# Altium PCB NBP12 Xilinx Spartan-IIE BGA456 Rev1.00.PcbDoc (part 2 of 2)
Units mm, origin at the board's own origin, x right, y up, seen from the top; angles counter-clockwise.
Board outline 69 x 80.99 mm, 4 copper layers (Top Layer, MidLayer1, InternalPlane1, Bottom Layer); 54 components, 265 nets, 866 pads, 396 vias.
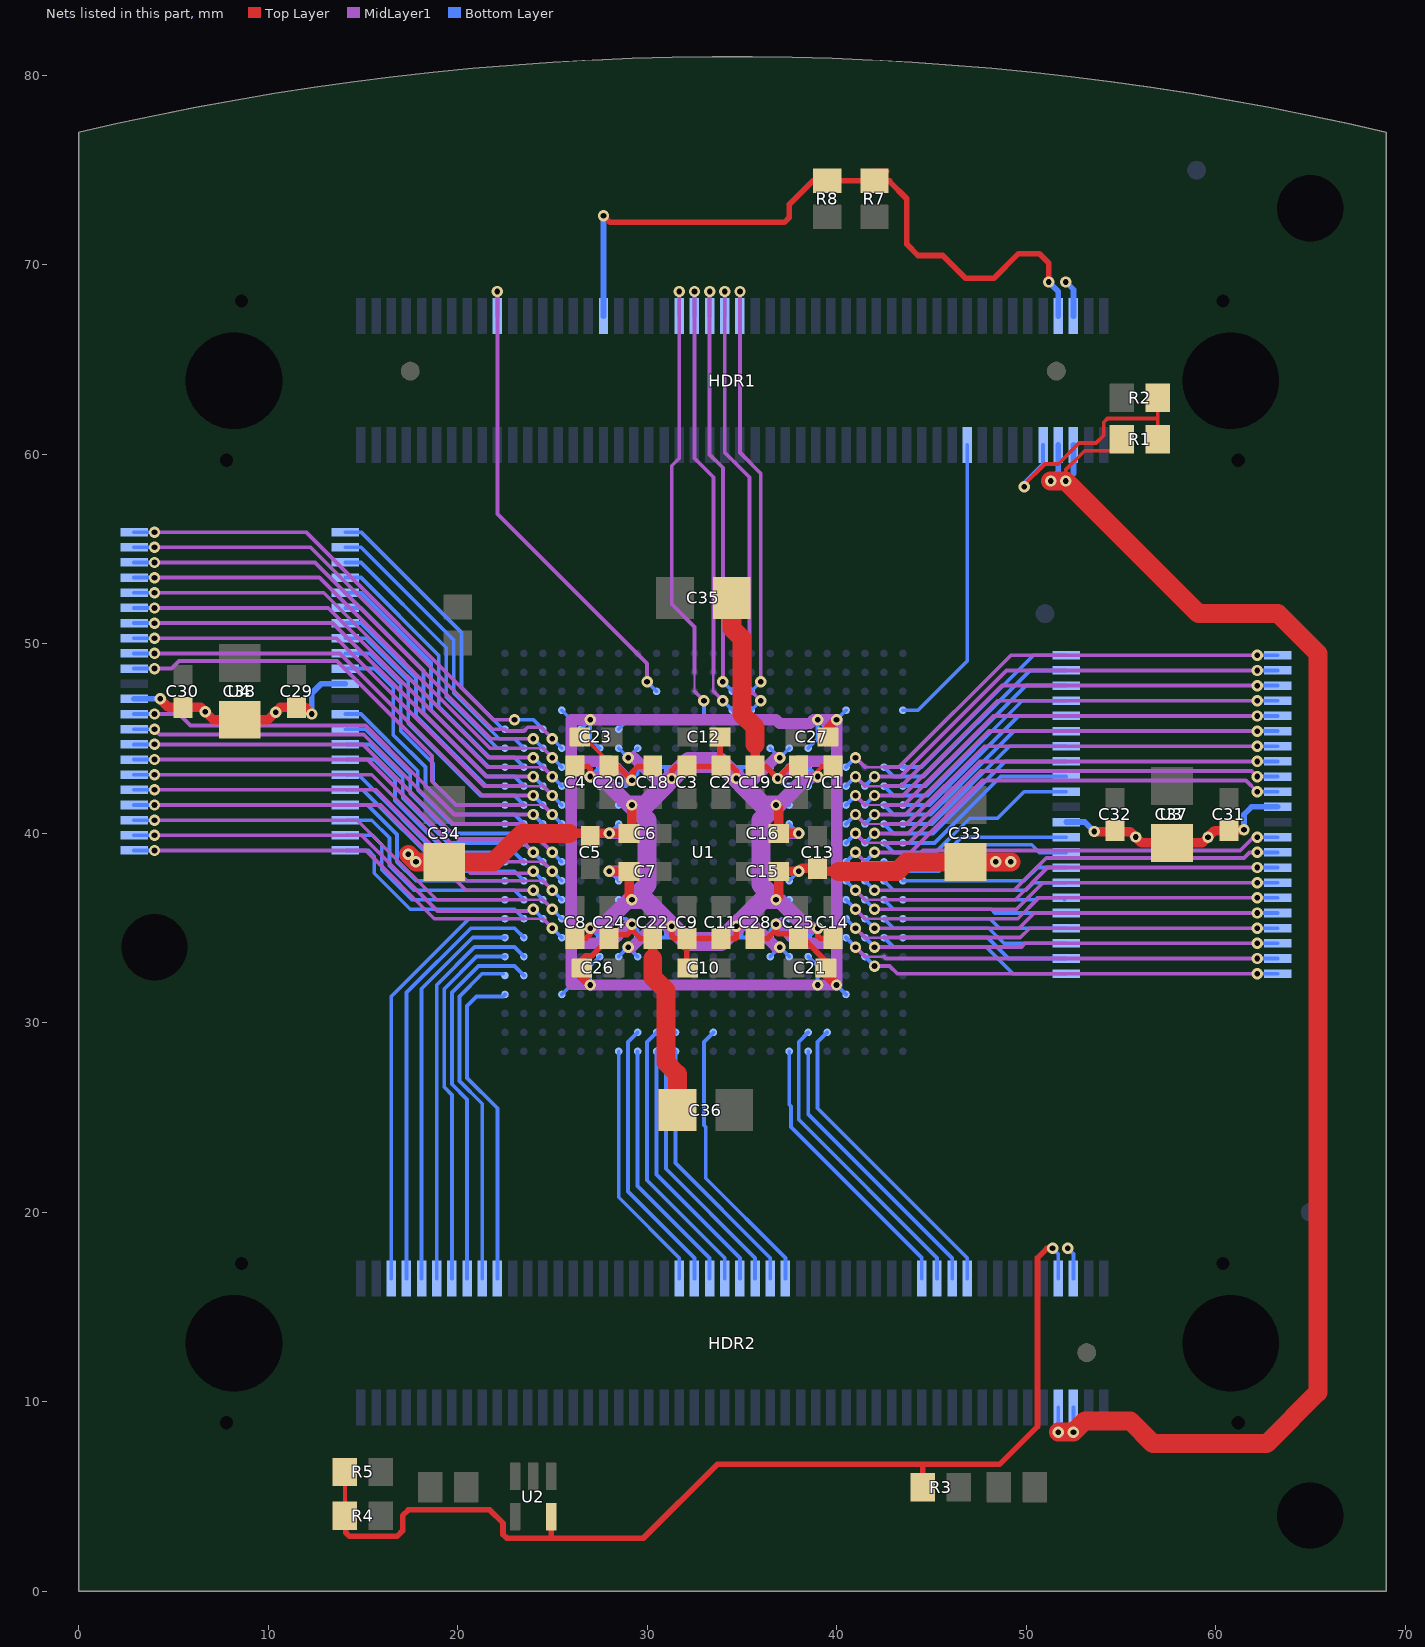
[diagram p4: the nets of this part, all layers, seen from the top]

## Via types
v1: diameter 0.6, hole 0.3, Top Layer to Bottom Layer, tented top, 396 vias

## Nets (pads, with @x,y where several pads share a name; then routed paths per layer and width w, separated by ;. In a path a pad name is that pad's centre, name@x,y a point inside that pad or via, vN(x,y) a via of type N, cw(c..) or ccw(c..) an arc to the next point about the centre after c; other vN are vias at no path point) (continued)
SP12: HDR2.82 U1.AA5 | length 16.5
  Bottom Layer w0.2: U1.AA5@39.5,29.5 39,29 39,25.5 46.9,17.6 HDR2.82@46.9,16.5
SP13: HDR2.80 U1.AB6 | length 15.1
  Bottom Layer w0.2: U1.AB6@38.5,28.5 38.5,25.2 46.1,17.6 HDR2.80@46.1,16.5
SP14: HDR2.78 U1.AA6 | length 16.2
  Bottom Layer w0.2: U1.AA6@38.5,29.5 38,29 38,24.9 45.3,17.6 HDR2.78@45.3,16.5
SP15: HDR2.76 U1.AB7 | length 14.9
  Bottom Layer w0.2: U1.AB7@37.5,28.5 37.5,25.7 37.6,25.6 37.6,24.5 44.5,17.6 HDR2.76@44.5,16.5
SPI_CLK: HDR1.46 U1.D10 | length 24.2
  MidLayer1 w0.127: 33.5,47.5 33.5,48.5
  MidLayer1 w0.2: v1(32.5,68.6) 32.5,59.8 33.5,58.8 33.5,48.5 ; 33.5,47.5 v1(34,47)
  Bottom Layer w0.2: HDR1.46@32.5,67.3 v1(32.5,68.6) ; v1(34,47) U1.D10@34.5,46.5
SPI_DIN: HDR1.44 U1.E16 | length 29.4
  MidLayer1 w0.127: 32.5,47.5 32.5,48.5
  MidLayer1 w0.2: v1(31.7,68.6) 31.7,59.8 31.3,59.4 31.3,52.1 32.5,50.9 32.5,48.5 ; 32.5,47.5 v1(33,47)
  Bottom Layer w0.2: U1.E16@28.5,45.5 29,46 32.8,46 33,46.2 v1(33,47) ; HDR1.44@31.7,67.3 v1(31.7,68.6)
SPI_DOUT: HDR1.50 U1.D9 | length 24.4
  MidLayer1 w0.2: v1(34.1,68.6) 34.1,60.1 35.4,58.8 35.4,47.6 v1(36,47)
  Bottom Layer w0.2: HDR1.50@34.1,67.3 v1(34.1,68.6) ; U1.D9@35.5,46.5 v1(36,47)
SPI_MODE: HDR1.52 U1.C9 | length 23.1
  MidLayer1 w0.2: v1(34.9,68.6) 34.9,60.1 36,59 v1(36,48)
  Bottom Layer w0.2: HDR1.52@34.9,67.3 v1(34.9,68.6) ; U1.C9@35.5,47.5 v1(36,48)
SPI_SEL: HDR1.48 U1.C10 | length 22.9
  MidLayer1 w0.2: v1(33.3,68.6) 33.3,60 34,59.3 v1(34,48)
  Bottom Layer w0.2: HDR1.48@33.3,67.3 v1(33.3,68.6) ; v1(34,48) U1.C10@34.5,47.5
SRAM0_A0: U1.J4 U3.5 | length 25.1
  MidLayer1 w0.127: 41.5,41.5 42.5,41.5
  MidLayer1 w0.2: v1(41,42) 41.5,41.5 ; 42.5,41.5 43.566,41.5 48.266,46.2 v1(62.2,46.2)
  Bottom Layer w0.2: U1.J4@40.5,41.5 v1(41,42) ; v1(62.2,46.2) U3.5@63.275,46.2
SRAM0_A1: U1.J3 U3.4 | length 24.1
  MidLayer1 w0.2: v1(42,42) 43.5,42 48.5,47 v1(62.2,47)
  Bottom Layer w0.2: U1.J3@41.5,41.5 v1(42,42) ; v1(62.2,47) U3.4@63.275,47
SRAM0_A2: U1.H4 U3.3 | length 25.4
  MidLayer1 w0.127: 41.5,42.5 42.5,42.5
  MidLayer1 w0.2: v1(41,43) 41.5,42.5 ; 42.5,42.5 43.434,42.5 48.734,47.8 v1(62.2,47.8)
  Bottom Layer w0.2: U1.H4@40.5,42.5 v1(41,43) ; v1(62.2,47.8) U3.3@63.275,47.8
SRAM0_A3: U1.H3 U3.2 | length 24.3
  MidLayer1 w0.2: v1(42,43) 43.369,43 48.969,48.6 v1(62.2,48.6)
  Bottom Layer w0.2: U1.H3@41.5,42.5 v1(42,43) ; v1(62.2,48.6) U3.2@63.275,48.6
SRAM0_A4: U1.G4 U3.1 | length 25.6
  MidLayer1 w0.127: 41.5,43.5 42.5,43.5
  MidLayer1 w0.2: v1(41,44) 41.5,43.5 ; 42.5,43.5 43.303,43.5 49.203,49.4 v1(62.2,49.4)
  Bottom Layer w0.2: U1.G4@40.5,43.5 v1(41,44) ; v1(62.2,49.4) U3.1@63.275,49.4
SRAM0_A5: U1.G1 U3.44 | length 11.1
  Bottom Layer w0.2: U1.G1@43.5,43.5 44.5,43.5 50.4,49.4 U3.44@52.125,49.4
SRAM0_A6: U1.G2 U3.43 | length 12.2
  Bottom Layer w0.2: U1.G2@42.5,43.5 43,43 44.6,43 50.2,48.6 U3.43@52.125,48.6
SRAM0_A7: U1.H1 U3.42 | length 10.8
  Bottom Layer w0.2: U1.H1@43.5,42.5 44.7,42.5 50,47.8 U3.42@52.125,47.8
SRAM0_A8: U1.P1 U3.28 | length 8.8
  Bottom Layer w0.2: U1.P1@43.5,36.5 50.5,36.5 50.6,36.6 U3.28@52.125,36.6 U3.28@52.025,36.5
SRAM0_A9: U1.P2 U3.27 | length 9.9
  Bottom Layer w0.2: U1.P2@42.5,36.5 43,36 48.163,36 48.363,35.8 U3.27@52.125,35.8
SRAM0_A10: U1.R1 U3.26 | length 8.8
  Bottom Layer w0.2: U1.R1@43.5,35.5 48.097,35.5 48.597,35 U3.26@52.125,35
SRAM0_A11: U1.R2 U3.25 | length 10.2
  Bottom Layer w0.2: U1.R2@42.5,35.5 43,35 48.031,35 48.831,34.2 U3.25@52.125,34.2
SRAM0_A12: U1.T1 U3.24 | length 9.1
  Bottom Layer w0.2: U1.T1@43.5,34.5 47.966,34.5 49.066,33.4 U3.24@52.125,33.4
SRAM0_A13: U1.T2 U3.23 | length 10.4
  Bottom Layer w0.2: U1.T2@42.5,34.5 43,34 47.9,34 49.3,32.6 U3.23@52.125,32.6
SRAM0_A14: U1.U3 U3.22 | length 22.1
  MidLayer1 w0.2: v1(42,33) 42.8,33 43.2,32.6 v1(62.2,32.6)
  Bottom Layer w0.2: U1.U3@41.5,33.5 v1(42,33) ; v1(62.2,32.6) U3.22@63.275,32.6
SRAM0_A15: U1.T4 U3.21 | length 23.2
  MidLayer1 w0.127: 41.5,33.5 42.5,33.5
  MidLayer1 w0.2: v1(41,34) 41.5,33.5 ; 42.5,33.5 42.6,33.4 v1(62.2,33.4)
  Bottom Layer w0.2: U1.T4@40.5,34.5 v1(41,34) ; v1(62.2,33.4) U3.21@63.275,33.4
SRAM0_A16: U1.T3 U3.20 | length 22.1
  MidLayer1 w0.2: v1(42,34) 49.76,34 49.96,34.2 v1(62.2,34.2)
  Bottom Layer w0.2: U1.T3@41.5,34.5 v1(42,34) ; v1(62.2,34.2) U3.20@63.275,34.2
SRAM0_A17: U1.R4 U3.19 | length 23.4
  MidLayer1 w0.127: 41.5,34.5 42.5,34.5
  MidLayer1 w0.2: v1(41,35) 41.5,34.5 ; 42.5,34.5 49.694,34.5 50.194,35 v1(62.2,35)
  Bottom Layer w0.2: U1.R4@40.5,35.5 v1(41,35) ; v1(62.2,35) U3.19@63.275,35
SRAM0_A18: U1.R3 U3.18 | length 22.3
  MidLayer1 w0.2: v1(42,35) 49.628,35 50.428,35.8 v1(62.2,35.8)
  Bottom Layer w0.2: U1.R3@41.5,35.5 v1(42,35) ; v1(62.2,35.8) U3.18@63.275,35.8
SRAM0_D0: U1.K4 U3.7 | length 24.9
  MidLayer1 w0.127: 41.5,40.5 42.5,40.5
  MidLayer1 w0.2: v1(41,41) 41.5,40.5 ; 42.5,40.5 43.697,40.5 47.797,44.6 v1(62.2,44.6)
  Bottom Layer w0.2: U1.K4@40.5,40.5 v1(41,41) ; v1(62.2,44.6) U3.7@63.275,44.6
SRAM0_D1: U1.L3 U3.8 | length 23.6
  MidLayer1 w0.2: v1(42,40) 43.763,40 46.034,42.271 47.563,43.8 v1(62.2,43.8)
  Bottom Layer w0.2: U1.L3@41.5,39.5 v1(42,40) ; v1(62.2,43.8) U3.8@63.275,43.8
SRAM0_D2: U1.L4 U3.9 | length 24.9
  MidLayer1 w0.127: 41.5,39.5 42.5,39.5
  MidLayer1 w0.2: v1(41,40) 41.5,39.5 ; 42.5,39.5 43.828,39.5 47.628,43.3 61.9,43.3 v1(62.2,43)
  Bottom Layer w0.2: U1.L4@40.5,39.5 v1(41,40) ; v1(62.2,43) U3.9@63.275,43
SRAM0_D3: U1.M3 U3.10 | length 23.8
  MidLayer1 w0.2: v1(42,39) 43.894,39 47.694,42.8 61.6,42.8 v1(62.2,42.2)
  Bottom Layer w0.2: U1.M3@41.5,38.5 v1(42,39) ; v1(62.2,42.2) U3.10@63.275,42.2
SRAM0_D4: U1.M4 U3.13 | length 23.8
  MidLayer1 w0.2: v1(41,39) 41.564,38.436 43.896,38.436 44.56,39.1 61.3,39.1 62,39.8 v1(62.2,39.8)
  Bottom Layer w0.2: U1.M4@40.5,38.5 v1(41,39) ; v1(62.2,39.8) U3.13@63.275,39.8
SRAM0_D5: U1.N3 U3.14 | length 22.8
  MidLayer1 w0.2: v1(42,37) 49.366,37 51.066,38.7 61.5,38.7 61.8,39 v1(62.2,39)
  Bottom Layer w0.2: U1.N3@41.5,37.5 v1(42,37) ; v1(62.2,39) U3.14@63.275,39
SRAM0_D6: U1.N4 U3.15 | length 23.9
  MidLayer1 w0.127: 41.5,36.5 42.5,36.5
  MidLayer1 w0.2: v1(41,37) 41.5,36.5 ; 42.5,36.5 49.431,36.5 51.131,38.2 v1(62.2,38.2)
  Bottom Layer w0.2: U1.N4@40.5,37.5 v1(41,37) ; v1(62.2,38.2) U3.15@63.275,38.2
SRAM0_D7: U1.P3 U3.16 | length 22.6
  MidLayer1 w0.2: v1(42,36) 49.497,36 50.897,37.4 v1(62.2,37.4)
  Bottom Layer w0.2: U1.P3@41.5,36.5 v1(42,36) ; v1(62.2,37.4) U3.16@63.275,37.4
SRAM0_D8: U1.N2 U3.29 | length 10
  Bottom Layer w0.2: U1.N2@42.5,37.5 43,37 50,37 50.4,37.4 U3.29@52.125,37.4
SRAM0_D9: U1.N1 U3.30 | length 8.9
  Bottom Layer w0.2: U1.N1@43.5,37.5 49.9,37.5 50.6,38.2 U3.30@52.125,38.2
SRAM0_D10: U1.M2 U3.31 | length 10.6
  Bottom Layer w0.2: U1.M2@42.5,38.5 43,38 45.4,38 46.8,39.4 50.3,39.4 50.7,39 U3.31@52.125,39
SRAM0_D11: U1.M1 U3.32 | length 9.2
  Bottom Layer w0.2: U1.M1@43.5,38.5 45.294,38.5 46.594,39.8 U3.32@52.125,39.8
SRAM0_D12: U1.L2 U3.35 | length 11.2
  Bottom Layer w0.2: U1.L2@42.5,39.5 43,39 45.228,39 47.028,40.8 48.5,40.8 49.9,42.2 U3.35@52.125,42.2
SRAM0_D13: U1.L1 U3.36 | length 10.1
  Bottom Layer w0.2: U1.L1@43.5,39.5 45.163,39.5 48.663,43 U3.36@52.125,43
SRAM0_D14: U1.K2 U3.37 | length 11.4
  Bottom Layer w0.2: U1.K2@42.5,40.5 43,40 45.097,40 48.897,43.8 U3.37@52.125,43.8
SRAM0_D15: U1.K1 U3.38 | length 10.3
  Bottom Layer w0.2: U1.K1@43.5,40.5 45.031,40.5 49.131,44.6 U3.38@52.125,44.6
SRAM0_E: U1.K3 U3.6 | length 23.8
  MidLayer1 w0.2: v1(42,41) 43.631,41 48.031,45.4 v1(62.2,45.4)
  Bottom Layer w0.2: U1.K3@41.5,40.5 v1(42,41) ; v1(62.2,45.4) U3.6@63.275,45.4
SRAM0_LB: U1.J2 U3.39 | length 11.7
  Bottom Layer w0.2: U1.J2@42.5,41.5 43,41 44.966,41 49.366,45.4 U3.39@52.125,45.4
SRAM0_OE: U1.H2 U3.41 | length 11.9
  Bottom Layer w0.2: U1.H2@42.5,42.5 43,42 44.8,42 49.8,47 U3.41@52.125,47
SRAM0_UB: U1.J1 U3.40 | length 10.6
  Bottom Layer w0.2: U1.J1@43.5,41.5 44.9,41.5 49.6,46.2 U3.40@52.125,46.2
SRAM0_W: U1.P4 U3.17 | length 23.6
  MidLayer1 w0.127: 41.5,35.5 42.5,35.5
  MidLayer1 w0.2: v1(41,36) 41.5,35.5 ; 42.5,35.5 49.563,35.5 50.663,36.6 v1(62.2,36.6)
  Bottom Layer w0.2: U1.P4@40.5,36.5 v1(41,36) ; v1(62.2,36.6) U3.17@63.275,36.6
SRAM1_A0: U1.G22 U4.5 | length 13.7
  Bottom Layer w0.2: U4.5@14.075,52.7 14.9,52.7 18.6,49 18.6,46.531 21.631,43.5 U1.G22@22.5,43.5
SRAM1_A1: U1.G21 U4.4 | length 15.2
  Bottom Layer w0.2: U4.4@14.075,53.5 14.9,53.5 19,49.4 19,46.697 21.697,44 23,44 U1.G21@23.5,43.5
SRAM1_A2: U1.F22 U4.3 | length 14
  Bottom Layer w0.2: U4.3@14.075,54.3 14.9,54.3 19.4,49.8 19.4,47.2 22.1,44.5 U1.F22@22.5,44.5
SRAM1_A3: U1.F21 U4.2 | length 15.5
  Bottom Layer w0.2: U4.2@14.075,55.1 14.9,55.1 19.8,50.2 19.8,47.4 22.2,45 23,45 U1.F21@23.5,44.5
SRAM1_A4: U1.E22 U4.1 | length 14.4
  Bottom Layer w0.2: U4.1@14.075,55.9 14.9,55.9 20.2,50.6 20.2,47.7 22.4,45.5 U1.E22@22.5,45.5
SRAM1_A5: U1.E20 U4.44 | length 26.6
  MidLayer1 w0.2: v1(4,55.9) 12,55.9 21.9,46 v1(23,46)
  Bottom Layer w0.2: U4.44@2.925,55.9 v1(4,55.9) ; v1(23,46) 24,46 ; 24,46 U1.E20@24.5,45.5 24,46
SRAM1_A6: U1.F19 U4.43 | length 27.1
  MidLayer1 w0.2: v1(4,55.1) 12.234,55.1 21.834,45.5 22.5,45.5 22.6,45.4 23.5,45.4 23.7,45.6 24.4,45.6 v1(25,45)
  Bottom Layer w0.2: U4.43@2.925,55.1 v1(4,55.1) ; v1(25,45) U1.F19@25.5,44.5
SRAM1_A7: U1.F20 U4.42 | length 25.6
  MidLayer1 w0.2: v1(4,54.3) 12.469,54.3 21.769,45 v1(24,45)
  Bottom Layer w0.2: U4.42@2.925,54.3 v1(4,54.3) ; v1(24,45) U1.F20@24.5,44.5
SRAM1_A8: U1.N20 U4.28 | length 24
  MidLayer1 w0.2: v1(4,43.1) 15.472,43.1 20.672,37.9 23.9,37.9 v1(24,38)
  Bottom Layer w0.2: U4.28@2.925,43.1 v1(4,43.1) ; v1(24,38) U1.N20@24.5,37.5
SRAM1_A9: U1.P19 U4.27 | length 25
  MidLayer1 w0.127: 23.5,37.5 24.5,37.5
  MidLayer1 w0.2: v1(4,42.3) 15.706,42.3 20.506,37.5 23.5,37.5 ; 24.5,37.5 v1(25,37)
  Bottom Layer w0.2: U4.27@2.925,42.3 v1(4,42.3) ; v1(25,37) U1.P19@25.5,36.5
SRAM1_A10: U1.P20 U4.26 | length 23.6
  MidLayer1 w0.2: v1(4,41.5) 15.94,41.5 20.44,37 v1(24,37)
  Bottom Layer w0.2: U4.26@2.925,41.5 v1(4,41.5) ; v1(24,37) U1.P20@24.5,36.5
SRAM1_A11: U1.R19 U4.25 | length 24.7
  MidLayer1 w0.127: 23.5,36.5 24.5,36.5
  MidLayer1 w0.2: v1(4,40.7) 14.7,40.7 18.9,36.5 23.5,36.5 ; 24.5,36.5 v1(25,36)
  Bottom Layer w0.2: U4.25@2.925,40.7 v1(4,40.7) ; v1(25,36) U1.R19@25.5,35.5
SRAM1_A12: U1.R20 U4.24 | length 23.5
  MidLayer1 w0.2: v1(4,39.9) 14.934,39.9 18.934,35.9 23.9,35.9 v1(24,36)
  Bottom Layer w0.2: U4.24@2.925,39.9 v1(4,39.9) ; v1(24,36) U1.R20@24.5,35.5
SRAM1_A13: U1.T19 U4.23 | length 24.5
  MidLayer1 w0.127: 23.5,35.5 24.5,35.5
  MidLayer1 w0.2: v1(4,39.1) 15.169,39.1 18.769,35.5 23.5,35.5 ; 24.5,35.5 v1(25,35)
  Bottom Layer w0.2: U4.23@2.925,39.1 v1(4,39.1) ; v1(25,35) U1.T19@25.5,34.5
SRAM1_A14: U1.R21 U4.22 | length 11.4
  Bottom Layer w0.2: U4.22@14.075,39.1 15.3,39.1 15.6,38.8 15.6,37.9 17.5,36 23,36 U1.R21@23.5,35.5
SRAM1_A15: U1.P22 U4.21 | length 10.6
  Bottom Layer w0.2: U4.21@14.075,39.9 15.5,39.9 16,39.4 16,38.1 17.6,36.5 U1.P22@22.5,36.5
SRAM1_A16: U1.P21 U4.20 | length 12
  Bottom Layer w0.2: U4.20@14.075,40.7 15.472,40.7 16.4,39.772 16.4,38.3 17.7,37 23,37 U1.P21@23.5,36.5
SRAM1_A17: U1.N22 U4.19 | length 10.9
  Bottom Layer w0.2: U4.19@14.075,41.5 15.237,41.5 16.8,39.937 16.8,38.5 17.8,37.5 U1.N22@22.5,37.5
SRAM1_A18: U1.N21 U4.18 | length 11.4
  Bottom Layer w0.2: U4.18@14.075,42.3 15.003,42.3 19.303,38 23,38 U1.N21@23.5,37.5
SRAM1_D0: U1.H22 U4.7 | length 13.2
  Bottom Layer w0.2: U4.7@14.075,51.1 14.9,51.1 17.8,48.2 17.8,46.2 21.5,42.5 U1.H22@22.5,42.5
SRAM1_D1: U1.J21 U4.8 | length 14.4
  Bottom Layer w0.2: U4.8@14.075,50.3 15.134,50.3 17.4,48.034 17.4,45.8 21.2,42 23,42 U1.J21@23.5,41.5
SRAM1_D2: U1.J22 U4.9 | length 13.8
  Bottom Layer w0.2: U4.9@14.075,49.5 15.369,49.5 17,47.869 17,45.4 18.7,43.7 18.7,42.7 19.9,41.5 U1.J22@22.5,41.5
SRAM1_D3: U1.K21 U4.10 | length 14.9
  Bottom Layer w0.2: U4.10@14.075,48.7 15.603,48.7 16.6,47.703 16.6,45.2 18.3,43.5 18.3,42.5 19.8,41 23,41 U1.K21@23.5,40.5
SRAM1_D4: U1.K22 U4.13 | length 11.4
  Bottom Layer w0.2: U4.13@14.075,46.3 14.9,46.3 17.9,43.3 17.9,42.3 19.7,40.5 U1.K22@22.5,40.5
SRAM1_D5: U1.L21 U4.14 | length 12.5
  Bottom Layer w0.2: U4.14@14.075,45.5 15.134,45.5 17.5,43.134 17.5,42.1 19.6,40 23,40 U1.L21@23.5,39.5
SRAM1_D6: U1.L22 U4.15 | length 11.2
  Bottom Layer w0.2: U4.15@14.075,44.7 15.369,44.7 17.1,42.969 17.1,41.9 19.5,39.5 U1.L22@22.5,39.5
SRAM1_D7: U1.M21 U4.16 | length 12.3
  Bottom Layer w0.2: U4.16@14.075,43.9 15.603,43.9 16.7,42.803 16.7,41.734 19.434,39 23,39 U1.M21@23.5,38.5
SRAM1_D8: U1.N19 U4.29 | length 25.2
  MidLayer1 w0.127: 23.5,38.5 24.5,38.5
  MidLayer1 w0.2: v1(4,43.9) 15.237,43.9 20.637,38.5 23.5,38.5 ; 24.5,38.5 v1(25,38)
  Bottom Layer w0.2: U4.29@2.925,43.9 v1(4,43.9) ; v1(25,38) U1.N19@25.5,37.5
SRAM1_D9: U1.M20 U4.30 | length 24.1
  MidLayer1 w0.2: v1(4,44.7) 15.003,44.7 20.003,39.7 23.3,39.7 v1(24,39)
  Bottom Layer w0.2: U4.30@2.925,44.7 v1(4,44.7) ; v1(24,39) U1.M20@24.5,38.5
SRAM1_D10: U1.M19 U4.31 | length 25.5
  MidLayer1 w0.2: v1(4,45.5) 4.275,45.225 15.044,45.225 19.769,40.5 23.5,40.5 v1(25,39)
  Bottom Layer w0.2: U4.31@2.925,45.5 v1(4,45.5) ; v1(25,39) U1.M19@25.5,38.5
SRAM1_D11: U1.K20 U4.32 | length 24
  MidLayer1 w0.2: v1(4,46.3) 5.3,46.3 5.9,45.7 15.134,45.7 17.634,43.2 19.834,41 v1(24,41)
  Bottom Layer w0.2: U4.32@2.925,46.3 v1(4,46.3) ; v1(24,41) U1.K20@24.5,40.5
SRAM1_D12: U1.K19 U4.35 | length 27.1
  MidLayer1 w0.127: 23.5,41.5 24.5,41.5
  MidLayer1 w0.2: v1(4,48.7) 4.9,48.7 5.3,49.1 13.634,49.1 18.649,44.085 18.649,42.751 19.9,41.5 23.5,41.5 ; 24.5,41.5 v1(25,41)
  Bottom Layer w0.2: U4.35@2.925,48.7 v1(4,48.7) ; v1(25,41) U1.K19@25.5,40.5
SRAM1_D13: U1.J20 U4.36 | length 24.9
  MidLayer1 w0.2: v1(4,49.5) 13.8,49.5 21.3,42 v1(24,42)
  Bottom Layer w0.2: U4.36@2.925,49.5 v1(4,49.5) ; v1(24,42) U1.J20@24.5,41.5
SRAM1_D14: U1.J19 U4.37 | length 26.2
  MidLayer1 w0.127: 23.5,42.5 24.5,42.5
  MidLayer1 w0.2: v1(4,50.3) 13.6,50.3 21.4,42.5 23.5,42.5 ; 24.5,42.5 v1(25,42)
  Bottom Layer w0.2: U4.37@2.925,50.3 v1(4,50.3) ; v1(25,42) U1.J19@25.5,41.5
SRAM1_D15: U1.H20 U4.38 | length 25.1
  MidLayer1 w0.2: v1(4,51.1) 13.406,51.1 21.506,43 v1(24,43)
  Bottom Layer w0.2: U4.38@2.925,51.1 v1(4,51.1) ; v1(24,43) U1.H20@24.5,42.5
SRAM1_E: U1.H21 U4.6 | length 14.6
  Bottom Layer w0.2: U4.6@14.075,51.9 14.9,51.9 18.2,48.6 18.2,46.366 21.566,43 23,43 U1.H21@23.5,42.5
SRAM1_LB: U1.H19 U4.39 | length 26.5
  MidLayer1 w0.127: 23.5,43.5 24.5,43.5
  MidLayer1 w0.2: v1(4,51.9) 13.172,51.9 21.572,43.5 23.5,43.5 ; 24.5,43.5 v1(25,43)
  Bottom Layer w0.2: U4.39@2.925,51.9 v1(4,51.9) ; v1(25,43) U1.H19@25.5,42.5
SRAM1_OE: U1.G19 U4.41 | length 26.7
  MidLayer1 w0.127: 23.5,44.5 24.5,44.5
  MidLayer1 w0.2: v1(4,53.5) 12.703,53.5 21.703,44.5 23.5,44.5 ; 24.5,44.5 v1(25,44)
  Bottom Layer w0.2: U4.41@2.925,53.5 v1(4,53.5) ; v1(25,44) U1.G19@25.5,43.5
SRAM1_UB: U1.G20 U4.40 | length 25.4
  MidLayer1 w0.2: v1(4,52.7) 12.937,52.7 21.637,44 v1(24,44)
  Bottom Layer w0.2: U4.40@2.925,52.7 v1(4,52.7) ; v1(24,44) U1.G20@24.5,43.5
SRAM1_W: U1.M22 U4.17 | length 10.3
  Bottom Layer w0.2: U4.17@14.075,43.1 14.769,43.1 19.369,38.5 U1.M22@22.5,38.5
SW0: HDR2.44 U1.AB16 | length 13.3
  Bottom Layer w0.2: U1.AB16@28.5,28.5 28.5,20.8 31.7,17.6 HDR2.44@31.7,16.5
SW1: HDR2.46 U1.AA15 | length 14.7
  Bottom Layer w0.2: U1.AA15@29.5,29.5 29,29 29,21.1 32.5,17.6 HDR2.46@32.5,16.5
SW2: HDR2.48 U1.AB15 | length 13.6
  Bottom Layer w0.2: U1.AB15@29.5,28.5 29.5,21.4 33.3,17.6 HDR2.48@33.3,16.5
SW3: HDR2.50 U1.AA14 | length 14.9
  Bottom Layer w0.2: U1.AA14@30.5,29.5 30,29 30,21.7 34.1,17.6 HDR2.50@34.1,16.5
SW4: HDR2.52 U1.AB14 | length 13.8
  Bottom Layer w0.2: U1.AB14@30.5,28.5 30.5,22 34.9,17.6 HDR2.52@34.9,16.5
SW5: HDR2.54 U1.AA13 | length 15.2
  Bottom Layer w0.2: U1.AA13@31.5,29.5 31,29 31,22.3 35.7,17.6 HDR2.54@35.7,16.5
SW6: HDR2.56 U1.AB13 | length 14.1
  Bottom Layer w0.2: U1.AB13@31.5,28.5 31.5,22.6 36.5,17.6 HDR2.56@36.5,16.5
SW7: HDR2.58 U1.AA11 | length 15
  Bottom Layer w0.2: U1.AA11@33.5,29.5 33,29 33,24.6 33.1,24.5 33.1,21.8 37.3,17.6 HDR2.58@37.3,16.5
SWC0: HDR2.18 U1.V22 | length 18.2
  Bottom Layer w0.2: HDR2.18@21.3,16.5 21.3,25.731 20.1,26.931 20.1,31.4 21.3,32.6 U1.V22@22.4,32.6
SWC1: HDR2.16 U1.V21 | length 20
  Bottom Layer w0.2: HDR2.16@20.5,16.5 20.5,25.966 19.7,26.766 19.7,31.6 21.1,33 23,33 U1.V21@23.5,32.5
SWC2: HDR2.14 U1.U22 | length 19.4
  Bottom Layer w0.2: HDR2.14@19.7,16.5 19.7,26.2 19.3,26.6 19.3,31.8 21,33.5 U1.U22@22.5,33.5
SWC3: HDR2.6 U1.R22 | length 22.6
  Bottom Layer w0.2: HDR2.6@16.5,16.5 16.5,31.4 20.6,35.5 U1.R22@22.5,35.5
SWR0: HDR2.20 U1.W22 | length 17.3
  Bottom Layer w0.2: HDR2.20@22.1,16.5 22.1,25.497 20.5,27.097 20.5,30.9 21,31.4 22.4,31.4 U1.W22@22.5,31.5
SWR1: HDR2.12 U1.U21 | length 21.1
  Bottom Layer w0.2: HDR2.12@18.9,16.5 18.9,32 20.9,34 23,34 U1.U21@23.5,33.5
SWR2: HDR2.10 U1.T22 | length 20.8
  Bottom Layer w0.2: HDR2.10@18.1,16.5 18.1,31.8 20.8,34.5 U1.T22@22.5,34.5
SWR3: HDR2.8 U1.T21 | length 22.9
  Bottom Layer w0.2: HDR2.8@17.3,16.5 17.3,31.6 20.7,35 23,35 U1.T21@23.5,34.5
TEST: HDR1.81 U1.D1 | length 15.9
  Bottom Layer w0.2: U1.D1@43.5,46.5 44.3,46.5 46.9,49.1 HDR1.81@46.9,60.5
VCC: C1.2 C2.2 C3.2 C4.2 C5.2 C6.2 C7.2 C8.2 C9.2 C10.2 C11.2 C12.2 C13.2 C14.2 C15.2 C16.2 C29.2 C30.2 C31.2 C32.2 C33.1 C34.1 C37.1 C38.1 HDR1.34 HDR1.94 HDR1.96 HDR2.94 HDR2.96 R3.1 R4.1 R5.1 R7.1 R8.1 U1.F7 U1.F8 U1.F15 U1.F16 U1.G6 U1.G9 U1.G10 U1.G13 U1.G14 U1.G17 U1.H6 U1.H17 U1.J7 U1.J16 U1.K7 U1.K16 U1.N7 U1.N16 U1.P7 U1.P16 U1.R6 U1.R17 U1.T6 U1.T9 U1.T10 U1.T13 U1.T14 U1.T17 U1.U7 U1.U8 U1.U15 U1.U16 U2.5 U3.11 U3.33 U4.11 U4.33 | length 272.9
  Top Layer w0.2: R4.1@14.05,4 R5.1@14.05,6.3 ; v1(39,43) 39,43.3 39.25,43.55
  Top Layer w0.3: R4.1@14.05,4 14.1,3.95 14.1,3.1 14.3,2.9 16.8,2.9 17.1,3.2 17.1,4 17.4,4.3 21.7,4.3 22.4,3.6 22.4,3 22.6,2.8 29.8,2.8 33.7,6.7 48.6,6.7 50.6,8.7 50.6,17.6 51.1,18.1 v1(51.4,18.1) ; 24.9,2.8 24.95,2.85 U2.5@24.95,3.925 ; C4.2@26.2,43.55 26.85,43.55 27,43.4 v1(27,43) ; 26.75,34.45 27,34.7 v1(27,35) ; v1(27.7,72.6) 28.05,72.25 37.25,72.25 37.5,72.5 37.5,73.2 38.75,74.45 R8.1@39.5,74.45 42.8,74.45 42.8,74.4 43.7,73.5 43.7,71.1 44.3,70.5 45.6,70.5 46.8,69.3 48.3,69.3 49.6,70.6 50.7,70.6 51.2,70.1 v1(51.2,69.1) ; v1(31.3,35.1) 31.3,34.6 31.45,34.45 C9.2@32.1,34.45 ; v1(31.3,42.9) 31.3,43.3 31.55,43.55 C3.2@32.1,43.55 C2.2@33.9,43.55 34.45,43.55 34.7,43.3 v1(34.7,42.9) ; C10.2@32.15,32.9 32.1,32.95 C9.2@32.1,34.45 ; C2.2@33.85,43.6 C12.2@33.85,45.1 ; v1(34.7,35.1) 34.7,34.5 34.65,34.45 C11.2@33.9,34.45 C9.2@32.1,34.45 ; v1(38,38) v1@38.15,38.15 ; v1(39,35) 39,34.6 39.15,34.45 C14.2@39.8,34.45 ; 39.25,43.55 C1.2@39.8,43.55 ; R7.1@42,74.95 R7.1@42.65,74.95 ; R3.1@44.55,5.5 44.55,6.65
  Top Layer w0.5: v1(4.3,47.1) 4.75,46.65 C30.2@5.5,46.65 6.45,46.65 7.1,46 C38.1@8.5,46 10,46 10.65,46.65 11.95,46.65 v1(12.3,46.3) ; 25.9,40 26.85,40 C5.2@27,39.85 27.15,40 C6.2@29.05,40 29.2,40.15 v1(29.2,41.5) ; v1(28,38) C7.2@29.05,38 29.05,36.65 v1(29.2,36.5) ; v1(36.8,36.5) 36.95,36.65 C15.2@36.95,38 v1(38,38) ; v1(36.8,41.5) 36.95,41.35 C16.2@36.95,40 v1(38,40) ; v1@38.15,38.15 C13.2@39,38.15 39.15,38 40.1,38 ; C33.1@46.8,38.5 v1(48.4,38.5) ; v1(53.6,40.1) 54.65,40.1 55.5,40.1 56.1,39.5 C37.1@57.7,39.5 59.3,39.5 59.95,40.15 C31.2@60.7,40.15 60.75,40.2 v1(61.5,40.2)
  Top Layer w1: v1(17.4,38.9) v1(17.8,38.5) 21.9,38.5 23.4,40 25.9,40 ; 40.1,38 43.2,38 43.7,38.5 C33.1@46.8,38.5 v1(48.4,38.5) v1(49.2,38.5)
  MidLayer1 w0.6: v1(27,35) 27.7,35 v1(29.2,36.5) ; v1(27,43) 27.7,43 29.8,40.9 ; 27.4,35 29.05,36.65 v1@29.2,36.8 ; 27.4,43 v1@29.1,41.3 ; v1(28,38) 29.8,38 ; v1(28,40) 29.8,40 ; v1(29,34) 29.2,34 30.8,35.6 ; v1(29,44) 29.3,44 30.841,42.459 30.841,42.441 ; v1(31.3,42.9) 31.9,43.5 34.1,43.5 v1(34.7,42.9) ; 35.202,35.602 35.202,35.598 36.8,34 v1(37,34) ; 35.22,42.38 35.22,42.42 36.8,44 v1(37,44) ; 36.2,40 v1(38,40) ; 36.8,41.2 36.95,41.35 38.6,43 ; v1(36.8,41.5) 38.3,43 v1(39,43) ; 38.6,35 37.1,36.5 v1(36.8,36.5) 38.3,35 v1(39,35)
  MidLayer1 w1: v1(29.2,36.5) 30,37.3 30,40.7 v1(29.2,41.5) 29.9,41.5 32.2,43.8 33.8,43.8 36.1,41.5 v1(36.8,41.5) 36,40.7 36,37.3 v1(36.8,36.5) 36.1,36.5 33.9,34.3 32.1,34.3 29.9,36.5 v1(29.2,36.5)
  Bottom Layer w0.2: U1.T17@27.5,34.5 v1(27,35) U1.R17@27.5,35.5 ; U1.H17@27.5,42.5 v1(27,43) U1.G17@27.5,43.5 ; v1(28,38) U1.N16@28.5,37.5 ; v1(28,40) U1.K16@28.5,40.5 ; U1.U16@28.5,33.5 v1(29,34) U1.U15@29.5,33.5 ; U1.P16@28.5,36.5 v1(29.2,36.5) ; U1.J16@28.5,41.5 v1(29.2,41.5) ; U1.F16@28.5,44.5 v1(29,44) U1.F15@29.5,44.5 ; U1.T14@30.5,34.5 U1.T13@31.5,34.5 ; U1.G14@30.5,43.5 U1.G13@31.5,43.5 ; 31,34.5 31,34.8 v1(31.3,35.1) ; 31,43.5 31,43.2 v1(31.3,42.9) ; U1.T10@34.5,34.5 U1.T9@35.5,34.5 ; U1.G10@34.5,43.5 U1.G9@35.5,43.5 ; v1(34.7,35.1) 35,34.8 35,34.5 ; v1(34.7,42.9) 35,43.2 35,43.5 ; U1.U8@36.5,33.5 v1(37,34) U1.U7@37.5,33.5 ; U1.F8@36.5,44.5 v1(37,44) U1.F7@37.5,44.5 ; v1(36.8,36.5) U1.P7@37.5,36.5 ; v1(36.8,41.5) U1.J7@37.5,41.5 ; U1.N7@37.5,37.5 v1(38,38) ; U1.K7@37.5,40.5 v1(38,40) ; U1.T6@38.5,34.5 v1(39,35) U1.R6@38.5,35.5 ; U1.H6@38.5,42.5 v1(39,43) U1.G6@38.5,43.5 ; v1(51.4,18.1) 51.7,17.8 HDR2.94@51.7,16.5 ; v1(52.2,18.1) 52.5,17.8 HDR2.96@52.5,16.5
  Bottom Layer w0.3: U4.33@2.925,47.1 v1(4.3,47.1) ; 12.3,46.6 12.3,47.4 12.8,47.9 U4.11@14.075,47.9 ; HDR1.34@27.7,67.3 v1(27.7,72.6) ; v1(51.2,69.1) 51.7,68.6 HDR1.94@51.7,67.3 ; v1(52.1,69.1) 52.5,68.7 HDR1.96@52.5,67.3 ; U3.33@52.125,40.6 53.1,40.6 v1(53.6,40.1) ; v1(61.5,40.2) 61.5,41 61.9,41.4 U3.11@63.275,41.4
  other v1: 55.786,39.814 59.6,39.8 10.4,46.4 6.679,46.421
VCCINT: C17.2 C18.2 C19.2 C20.2 C21.2 C22.2 C23.2 C24.2 C25.2 C26.2 C27.2 C28.2 C35.1 C36.1 HDR1.93 HDR1.95 HDR2.93 HDR2.95 R1.1 U1.D4 U1.D19 U1.E5 U1.E18 U1.F6 U1.F17 U1.G7 U1.G8 U1.G15 U1.G16 U1.H7 U1.H16 U1.R7 U1.R16 U1.T7 U1.T8 U1.T15 U1.T16 U1.U6 U1.U17 U1.V5 U1.V18 U1.W4 U1.W19 | length 222.3
  Top Layer w0.2: C23.2@26.65,45.1 C20.2@28.1,43.65 ; v1(52.1,58.6) 52.1,59.2 53.1,60.2 54.45,60.2 R1.1@55.05,60.8
  Top Layer w0.3: C26.2@26.55,33.35 26.75,33.55 27.1,33.55 28.198,34.648 28.948,34.648 v1@29.2,34.9 ; C20.2@28.45,43.55 v1(29.2,42.8) 29.2,43.2 29.55,43.55 C18.2@30.3,43.55 ; v1(29.2,35.2) v1@29.2,34.9 ; C22.2@30.3,34.45 29.65,34.45 29.2,34.9 ; C28.2@35.7,34.45 36.35,34.45 36.8,34.9 ; C19.2@35.7,43.55 36.25,43.55 v1(36.9,42.9) C17.2@37.55,43.55 ; v1(36.8,35.2) 36.8,34.8 36.9,34.7 38,34.7 C25.2@38,34.45 38.25,34.45 C21.2@39.45,33.25
  Top Layer w0.5: C26.2@26.55,32.9 26.55,32.45 v1(27,32) ; C22.2@30.3,33.9 C22.2@30.3,34.45 ; C19.2@35.7,43.55 35.7,44.3 ; C21.2@39.45,32.9 39.45,32.55 v1(39.997,32.003) ; C27.2@39.55,45.1 39.55,45.55 v1(40,46)
  Top Layer w1: 30.3,33.4 30.3,32.4 31,31.7 31,27.9 31.6,27.3 C36.1@31.6,25.4 ; C35.1@34.471,52.429 34.471,50.829 35,50.3 35,46.3 35.7,45.6 35.7,44.7 ; v1(51.3,58.6) v1(52.1,58.6) 59.1,51.6 63.3,51.6 65.4,49.5 65.4,10.5 62.7,7.8 56.7,7.8 55.5,9 53.1,9 v1(52.5,8.4) v1(51.7,8.4)
  MidLayer1 w0.6: 26,32.059 26,36.3 26,41.7 26,46 ; 26,34.2 28.031,34.2 29.031,35.2 v1(29.2,35.2) ; 26,43.8 28.031,43.8 29.031,42.8 v1(29.2,42.8) ; 26.029,32.029 v1@26.97,32.029 ; 26.031,46 35.869,46 36.8,46 37,45.8 38.6,45.8 38.8,46 v1(40,46) ; 29,32 v1(27,32) v1@40,32 ; v1(36.8,35.2) 36.969,35.2 37.969,34.2 40,34.2 ; v1@40,32.005 40,34.2 ; 40,43.8 37.969,43.8 v1@37.069,42.9 ; v1@40,45.831 v1(40,46) ; v1@37.069,42.9 v1(36.9,42.9) v1@37.069,42.9 ; 40,34.2 v1(40,46)
  Bottom Layer w0.2: U1.W19@25.5,31.5 26,32 v1(27,32) ; U1.D19@25.5,46.5 26,46 v1(27,46) ; U1.V18@26.5,32.5 v1(27,32) ; U1.E18@26.5,45.5 v1(27,46) ; U1.U17@27.5,33.5 27,33 v1(27,32) ; U1.F17@27.5,44.5 27,45 v1(27,46) ; U1.R16@28.5,35.5 28.9,35.5 v1(29.2,35.2) ; U1.H16@28.5,42.5 28.9,42.5 v1(29.2,42.8) ; U1.G16@28.5,43.5 v1(29.2,42.8) ; U1.T16@28.6,34.6 U1.T16@28.5,34.5 v1(29.2,35.2) ; U1.T15@29.5,34.5 29.5,34.9 v1(29.2,35.2) ; U1.G15@29.5,43.5 29.5,43.1 v1(29.2,42.8) ; U1.T8@36.5,34.5 36.5,34.9 v1(36.8,35.2) ; U1.G8@36.5,43.5 36.5,43.3 v1(36.9,42.9) ; U1.T7@37.5,34.5 v1(36.8,35.2) ; U1.R7@37.5,35.5 37.1,35.5 v1(36.8,35.2) ; U1.H7@37.5,42.5 37.3,42.5 v1(36.9,42.9) ; U1.G7@37.5,43.5 v1(36.9,42.9) ; U1.U6@38.5,33.5 39,33 ; U1.F6@38.5,44.5 39,45 v1(39,46) ; v1@39,32.2 39,33 ; U1.V5@39.5,32.5 v1(39.997,32.003) ; U1.E5@39.5,45.5 v1(39,46) ; v1@39.995,32 v1(39,32) 39,33 ; v1@40,32 U1.W4@40.5,31.5 ; U1.D4@40.5,46.5 v1(40,46) v1(39,46) ; v1(51.7,8.4) HDR2.93@51.7,9.7 ; v1(52.5,8.4) HDR2.95@52.5,9.7
  Bottom Layer w0.3: v1(51.3,58.6) 51.7,59 HDR1.93@51.7,60.5 ; v1(52.1,58.6) 52.5,59 HDR1.95@52.5,60.5
VDRIVE: HDR1.20 U1.C14 | length 25.9
  MidLayer1 w0.2: v1(22.1,68.6) 22.1,56.86 30,48.96 v1(30,48)
  Bottom Layer w0.2: HDR1.20@22.1,67.3 v1(22.1,68.6) ; v1(30,48) U1.C14@30.5,47.5
VREF: HDR1.91 R1.2 R2.1 | length 13.6
  Top Layer w0.2: v1(49.9,58.3) 49.9,58.4 51,59.5 51.7,59.5 52.8,60.6 53.7,60.6 54.1,61 54.1,61.7 54.3,61.9 56.9,61.9 56.95,61.95 ; R1.2@56.95,60.8 56.95,61.95 ; R2.1@56.95,63 56.95,61.95
  Bottom Layer w0.2: v1@49.9,58.5 50.9,59.5 HDR1.91@50.9,60.5
pads on no net: HDR1.MH1 HDR1.MH2 HDR1.MH3 HDR1.MH4 HDR1.MH5 HDR1.MH6 HDR2.MH1 HDR2.MH2 HDR2.MH3 HDR2.MH4 HDR2.MH5 HDR2.MH6 U1.C4 U1.D3 U1.D5 U1.D6 U1.D7 U1.D8 U1.D11 U1.D20 U1.D21 U1.D22 U1.E7 U1.E8 U1.E9 U1.E10 U1.E11 U1.E12 U1.E13 U1.E14 U1.E15 U1.E17 U1.E19 U1.E21 U1.F5 U1.F9 U1.F10 U1.F11 U1.F12 U1.F13 U1.F14 U1.F18 U1.G5 U1.G18 U1.H5 U1.H18 U1.J5 U1.J6 U1.J17 U1.J18 U1.K5 U1.K6 U1.K17 U1.K18 U1.L5 U1.L6 U1.L17 U1.L18 U1.L19 U1.L20 U1.M5 U1.M6 U1.M17 U1.M18 U1.N5 U1.N6 U1.N17 U1.N18 U1.P5 U1.P6 U1.P17 U1.P18 U1.R5 U1.R18 U1.T5 U1.T18 U1.U4 U1.U9 U1.U10 U1.U11 U1.U12 U1.U13 U1.U14 U1.V6 U1.V7 U1.V8 U1.V9 U1.V10 U1.V11 U1.V12 U1.V13 U1.V14 U1.V15 U1.V16 U1.V17 U2.1

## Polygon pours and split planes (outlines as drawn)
GND on Top Layer "Top Layer-GND" (solid, remove dead copper, pour order 1001): 0,0 0,82.2 69,82.2 69,0
VCCINT on Top Layer "Top Layer-VCCINT" (solid, remove dead copper, pour order 1000): 23,29 23,49.019 43,49.019 43,29
VCC on MidLayer1 "MidLayer1-VCC" (solid, remove dead copper, pour order 1003): 0,0 0,82.9 69,82.9 69,0
VCCINT on MidLayer1 "MidLayer1-VCCINT" (solid, remove dead copper, pour order 1002): 24,48 24,30 42,30 42,47.999 23.987,47.999
GND on Bottom Layer "Bottom Layer-GND" (solid, remove dead copper, pour order 1004): 0,0.1 0,82.2 69,82.2 69,0 0,0
GND on InternalPlane1 (split plane): 36.237,80.589 37.974,80.559 39.71,80.509 41.446,80.439 43.181,80.348 44.914,80.238 46.647,80.108 48.377,79.957 50.106,79.787 51.833,79.597 53.557,79.387 55.279,79.157 56.998,78.907 58.714,78.637 60.427,78.347 62.136,78.038 63.842,77.709 65.543,77.36 67.241,76.992 68.598,76.681 68.598,0.402 0.402,0.402 0.403,76.681 1.759,76.992 3.457,77.36 5.158,77.709 6.864,78.038 8.573,78.347 10.286,78.637 12.002,78.907 13.721,79.157 15.443,79.387 17.167,79.597 18.894,79.787 20.623,79.957 22.353,80.108 24.086,80.238 25.819,80.348 27.554,80.439 29.29,80.509 31.026,80.559 32.763,80.589 34.5,80.599
VCC on InternalPlane1 (split plane): 52.698,69.258 52.698,69 52.698,68.8 52.698,65.342 51.658,64.302 45.6,64.302 45.561,64.294 45.528,64.272 42.849,61.593 42.826,61.56 42.819,61.521 42.819,55.863 35.428,48.472 35.406,48.439 35.398,48.4 35.398,46.5 35.406,46.461 35.428,46.428 35.498,46.358 35.498,43 35.498,42.9 35.498,42.542 35.258,42.302 34.242,42.302 34.002,42.542 34.002,42.7 34.002,43 33.994,43.039 33.972,43.072 33.672,43.372 33.639,43.394 33.6,43.402 32.5,43.402 32.461,43.394 32.428,43.372 32.128,43.072 32.106,43.039 32.098,43 32.098,42.542 31.858,42.302 30.842,42.302 30.602,42.542 30.602,43.358 31.142,43.898 33.2,43.898 33.239,43.906 33.272,43.928 34.472,45.128 34.494,45.161 34.502,45.2 34.502,46.358 34.597,46.453 34.619,46.486 34.627,46.525 34.627,48.475 34.627,48.525 34.619,48.564 34.597,48.597 34.502,48.692 34.502,48.9 34.502,50.158 40.605,56.261 40.627,56.294 40.635,56.333 40.635,62.491 44.642,66.498 49.7,66.498 49.739,66.506 49.772,66.528 50.372,67.128 50.472,67.228 50.494,67.261 50.502,67.3 50.502,69.258 50.842,69.598 52.358,69.598
VCC on InternalPlane1 (split plane): 60.798,40.458 60.798,39.442 60.258,38.902 57,38.902 56.961,38.894 56.928,38.872 56.228,38.172 56.206,38.139 56.198,38.1 56.198,24 56.198,22.742 52.828,19.372 52.806,19.339 52.798,19.3 52.798,19 52.798,17.942 52.358,17.502 51.242,17.502 50.902,17.842 50.902,18.5 50.902,19.358 54.572,23.028 54.594,23.061 54.602,23.1 54.602,36.4 54.594,36.439 54.572,36.472 53.572,37.472 53.539,37.494 53.5,37.502 47.742,37.502 47.402,37.842 47.402,39.058 47.742,39.398 51.2,39.398 51.239,39.406 51.272,39.428 52.942,41.098 60.158,41.098
VCC on InternalPlane1 (split plane): 18.798,40.458 18.798,39.9 18.798,38.6 18.798,38.242 18.228,37.672 18.058,37.502 17.642,37.502 17.472,37.672 11.972,43.172 9.472,45.672 9.439,45.694 9.4,45.702 6.342,45.702 5.702,46.342 5.702,46.858 6.142,47.298 11.958,47.298
VCCINT on InternalPlane1 (split plane): 52.598,58.858 52.598,58.242 51.928,57.572 49.858,55.502 48.4,55.502 48.361,55.494 48.328,55.472 41.528,48.672 41.506,48.639 41.498,48.6 41.498,46.842 41.358,46.702 40.9,46.702 40.861,46.694 40.828,46.672 40.628,46.472 40.428,46.272 40.406,46.239 40.398,46.2 40.398,45.442 37.358,42.402 36.542,42.402 36.402,42.542 36.402,43.1 36.402,43.258 36.542,43.398 37.1,43.398 37.139,43.406 37.172,43.428 37.663,43.919 37.685,43.952 37.693,43.991 37.693,44.191 37.693,45.749 39.342,47.398 40.2,47.398 40.239,47.406 40.272,47.428 40.572,47.728 40.594,47.761 40.602,47.8 40.602,49.858 47.542,56.798 49.4,56.798 49.439,56.806 49.472,56.828 50.772,58.128 50.794,58.161 50.802,58.2 50.802,58.6 50.802,58.858 51.042,59.098 52.358,59.098

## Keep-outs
Top Layer:
  circle w0.1: c17.5,64.4 r1.5
  circle w0.1: c51.6,64.4 r1.5
  circle w0.1: c53.2,12.6 r1.5
Bottom Layer:
  circle w0.1: c65,20 r1.5
  circle w0.1: c51,51.6 r1.5
  circle w0.1: c59,75 r1.5
Keep-Out Layer:
  the board outline again, w0.8

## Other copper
InternalPlane1 (plane layer: these items are gaps in the copper):
  lines w0.2: 11.4,47.4 12,47.4 ; 18.9,39.9 18.9,40.5 ; 32.9,44 33.2,44 ; 41.2,46.4 40.7,46.4 ; 12,47.4 18.9,40.5 ; 12,47.4 6.1,47.4 5.6,46.9 5.6,46.3 6.3,45.6 8.5,45.6 9.4,45.6 11.9,43.1 17.4,37.6 17.6,37.4 18.1,37.4 18.3,37.6 18.9,38.2 18.9,38.6 18.9,40.5 ; 30.5,43.4 30.5,42.5 30.8,42.2 31.1,42.2 31.9,42.2 32.2,42.5 32.2,43 32.5,43.3 33.4,43.3 33.6,43.3 33.9,43 33.9,42.7 33.9,42.5 34.2,42.2 35.3,42.2 35.6,42.5 35.6,42.9 35.6,43 35.6,46.4 35.5,46.5 35.5,48.4 42.921,55.82 42.921,61.521 45.6,64.2 48.2,64.2 51.7,64.2 52.8,65.3 52.8,68.8 52.8,69 52.8,69.3 52.4,69.7 50.8,69.7 50.4,69.3 50.4,67.3 50.3,67.2 49.7,66.6 47.7,66.6 44.6,66.6 40.533,62.533 40.533,56.333 34.4,50.2 34.4,48.9 34.4,48.65 34.525,48.525 34.525,48.475 34.525,46.525 34.4,46.4 34.4,45.2 33.2,44 ; 30.5,43.4 31.1,44 ; 30.5,43.4 31.1,44 ; 31.1,44 33.2,44 ; 37.591,43.991 37.591,44.191 ; 37.591,43.991 37.591,44.191 ; 37.591,43.991 37.1,43.5 36.7,43.5 36.5,43.5 36.3,43.3 36.3,43.1 36.3,42.5 36.5,42.3 37.4,42.3 40.5,45.4 40.5,46.2 40.7,46.4 ; 37.591,44.191 37.591,45.791 39.3,47.5 40.2,47.5 40.5,47.8 40.5,49.9 47.5,56.9 49.4,56.9 50.7,58.2 50.7,58.6 50.7,58.9 51,59.2 52.4,59.2 52.7,58.9 52.7,58.2 52,57.5 49.9,55.4 48.4,55.4 41.6,48.6 41.6,46.8 41.4,46.6 ; 40.7,46.4 40.9,46.6 41.4,46.6 ; 41.4,46.6 41.4,46.6 ; 47.3,37.8 47.3,39.1 47.7,39.5 48.9,39.5 51.2,39.5 52.9,41.2 60.2,41.2 60.9,40.5 60.9,39.4 60.3,38.8 57,38.8 56.3,38.1 56.3,24 56.3,22.7 52.9,19.3 52.9,19 52.9,17.9 52.4,17.4 51.2,17.4 50.8,17.8 50.8,18.5 50.8,19.4 54.5,23.1 54.5,36.4 53.5,37.4 47.7,37.4 47.3,37.8

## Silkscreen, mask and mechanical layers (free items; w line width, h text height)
Top Overlay:
  lines w0.08: 25,45.8 25.5,45.3 25.5,43.5 ; 27.3,41.9 27.3,41.6 27.5,41.4 ; 28.5,36.9 28.7,36.7 28.7,36.1 ; 30.7,38.7 30.8,38.7 30.9,38.6 31.2,38.6 ; 30.7,40.7 30.8,40.7 30.9,40.6 31.2,40.6 ; 30.9,45.8 31.4,45.3 31.4,43.5 ; 31,33.9 31,34.5 ; 31,43.5 31,44.1 ; 31.4,36.1 31.4,36.8 ; 33.2,41.9 33.2,41.4 33.5,41.1 ; 34.6,36.1 34.6,36.9 ; 34.7,39.3 35.3,39.3 ; 35,33.8 35,34.5 ; 35,43.5 35,44.2 35.1,44.3 ; 36.9,37.3 37.6,37.3 ; 37.299,33.784 37.3,33.785 37.3,34.5 ; 38.7,41.9 38.7,41.6 38.9,41.4 ; 31,44.1 31,44.1
Bottom Overlay:
  drawing of 850 lines, arcs and shapes, not listed
  text "REV 1.00" at 47.6,76.5 h1.3
  text "NBP12" at 54.9,76.4 h1.3
  text "1" at 13.97,58.42 h1
  text "1" at 14.224,7.62 h1
PCB Boundary:
  the board outline again, w0.25
  text "PCB boundary coincides with centre-line of tracks and arc" at 0,-12 h0.75
Gerber ID:
  text ".Layer_Name" at 0,-6 h0.75
Printout ID:
  text ".Printout_Name" at 0,-10 h0.75
Design Information:
  drawing of 719 lines, arcs and shapes, not listed
  text "NBP12 REV1.00" at 240.157,177.165 h1.27
  text "DESIGN INFORMATION" at 184.15,177.038 h1.52
  text "BOARD NAME:" at 221.742,177.038 h1.52
  text "BOARD TECHNOLOGY" at 184.15,174.498 h1.52
  text "BOARD SIZE (REFER ALSO PROFILING INFORMATION)" at 232.41,174.498 h1.27
  text "69.00mm" at 235.13,172.224 h1.52
  text "81.00mm" at 258.13,172.124 h1.52
  text "5mil" at 186.9,172 h1.52
  text "15.748mil" at 197.7,172 h1.52
  text "5mil" at 214.9,172 h1.52
  text "X" at 251.079,171.45 h1.78
  text "(MIN. TRACK/   PADS  /   CLEARANCE     IN 0.001'')" at 182.626,169.418 h1.27
  text "MINIMUM ANNULAR RING 0.05MM (0.002'') EXTERNAL PER IPC-2221 CLASS 3 LEVEL C AND IS THE" at 184.15,166.878 h1.27
  text "MANUFACTURING REGISTRATION ALLOWANCE" at 184.15,164.592 h1.27
  text "LAND SIZE CALCULATION MINIMUM - NOMINAL HOLE SIZE + 0.508MM (0.020'')" at 184.15,161.798 h1.27
  text "AS INSTRUCTED" at 270.18,157.404 h1.52
  text "X" at 221.793,157.277 h1.52
  text "CIRCUIT TYPE:" at 184.15,157.226 h1.52
  text "SS" at 207.01,157.226 h1.27
  text "DS" at 224.79,157.226 h1.27
  text "X" at 239.395,157.226 h1.52
  text "PTH" at 242.57,157.226 h1.27
  text "ML" at 253.492,157.226 h1.27
  text "X" at 257.302,157.226 h1.52
  text "No. OFF" at 260.35,157.226 h1.27
  text "FINGER CONNECTOR DIM PER:" at 184.15,154.178 h1.52
  text "AS SHOWN" at 260.35,154.178 h1.27
  text "No. OFF TOTAL" at 200.914,151.384 h1.52
  text "ONE SIDE" at 242.57,151.384 h1.27
  text "BOTH SIDES" at 260.35,151.13 h1.27
  text "VIAS:" at 184.15,148.463 h1.52
  text "NONE" at 195.58,148.463 h1.14
  text "X" at 203.962,148.463 h1.52
  text "FEED THRU'" at 207.01,148.463 h1.14
  text "X" at 221.742,148.463 h1.52
  text "TENTED" at 224.79,148.463 h1.14
  text "BURIED LAYER SEQUENCE" at 242.57,148.463 h1.14
  text "UNIQUE DRILL" at 207.01,145.415 h1.14
  text "2 SIZE" at 224.79,145.415 h1.14
  text "BLIND LAYER SEQUENCE" at 242.57,145.415 h1.14
  text "Layer Stack Manager (Protel)" at 219.583,143.129 h1.27
  text "X" at 257.302,143.129 h1.52
  text "AS SHOWN" at 260.35,143.129 h1.27
  text "LAYER CONSTRUCTION PER:" at 184.15,143.002 h1.52
  text "Protel" at 265.176,140.462 h1.27
  text "(PFW)" at 275.463,140.335 h1.27
  text "ARTWORK:" at 184.15,140.208 h1.52
  text "MANUAL" at 207.01,140.208 h1.27
  text "DIGITISED" at 224.79,140.208 h1.27
  text "X" at 239.522,140.208 h1.52
  text "CAD" at 242.57,140.208 h1.27
  text "TYPE" at 253.492,140.208 h1.27
  text "ARTWORK/PATTERN MASTER LIST" at 184.15,135.509 h1.52
  text "DESCRIPTION" at 185.42,133.096 h1.27
  text "DRAWING No./CAD FILE REF." at 204.089,133.096 h1.27
  text "LAYER NAME" at 245.364,133.096 h1.27
  text "GERBER FILE REF" at 266.116,133.02 h1.27
  text "PCB FILE" at 183.866,130.632 h1.27
  text "BOCD_SpartanIIE_FG456" at 204.237,130.556 h1.27
  text "PcbDoc" at 235.479,130.556 h1.02
  text "Top Paste Mask" at 243.658,128.092 h1.02
  text "GTP" at 286.279,128.016 h1.27
  text "GERBER FILE" at 183.866,127.965 h1.27
  text "GTO" at 286.228,125.527 h1.27
  text "Top Overlay" at 243.658,125.501 h1.02
  text "GERBER FILE" at 183.866,125.425 h1.27
  text "Top Solder Mask" at 243.658,123.063 h1.02
  text "GTS" at 286.279,122.936 h1.27
  text "GERBER FILE" at 183.866,122.885 h1.27
  text "TOP LAYER" at 243.658,120.472 h1.02
  text "GTL" at 286.279,120.396 h1.27
  text "GERBER FILE" at 183.866,120.345 h1.27
  text "MIDLAYER1" at 243.84,118.237 h1.02
  text "G1" at 286.131,117.983 h1.27
  text "GERBER FILE" at 183.866,117.805 h1.27
  text "INTERNALPLANE1" at 243.586,115.57 h1.02
  text "GP1" at 286.131,115.443 h1.27
  text "GERBER FILE" at 183.866,115.265 h1.27
  text "BOTTOMLAYER" at 243.658,112.852 h1.02
  text "GBL" at 286.279,112.776 h1.27
  text "GERBER FILE" at 183.866,112.725 h1.27
  text "Bottom Solder Mask" at 243.658,110.363 h1.02
  text "GBS" at 286.279,110.236 h1.27
  text "GERBER FILE" at 183.866,110.185 h1.27
  text "Bottom Overlay" at 243.658,107.772 h1.02
  text "GBO" at 286.279,107.696 h1.27
  text "GERBER FILE" at 183.866,107.645 h1.27
  text "Bottom Paste Mask" at 243.658,105.283 h1.02
  text "GBP" at 286.279,105.156 h1.27
  text "GERBER FILE" at 183.866,105.105 h1.27
  text "PCB Boundary" at 243.658,102.692 h1.02
  text "GM1" at 286.279,102.616 h1.27
  text "GERBER FILE" at 183.866,102.565 h1.27
  text "APERTURE LIST" at 183.866,100.152 h1.27
  text "APR" at 236.479,100.076 h1.27
  text "DRILL REPORT" at 183.866,97.612 h1.27
  text "DRR" at 236.479,97.536 h1.27
  text "EXCELLON DRILL" at 183.866,95.072 h1.27
  text "TXT" at 236.479,94.996 h1.27
  text "MATERIAL:" at 184.15,74.422 h1.52
  text "GLASS FIBRE EPOXY RESIN NEMA GRADE FR4 (MIL-S-13949H)" at 209.804,74.168 h1.27
  text "X" at 207.137,74.041 h1.52
  text "THICKNESS:" at 192.024,71.247 h1.27
  text "0.8mm" at 209.804,71.247 h1.27
  text "1.2mm" at 227.457,71.247 h1.27
  text "1.6mm" at 245.11,71.247 h1.27
  text "2.4mm" at 262.89,71.247 h1.27
  text "3.2mm" at 280.67,71.247 h1.27
  text "X" at 242.697,71.12 h1.52
  text "TOLERANCE:" at 191.897,68.199 h1.27
  text "IN A/W IPC-D-300G CLASS" at 209.55,68.199 h1.27
  text "3 LEVEL B" at 244.475,68.199 h1.27
  text "OTHER +/-" at 262.89,68.199 h1.27
  text "X" at 207.137,68.072 h1.52
  text "BOW & TWIST:" at 189.484,65.151 h1.27
  text "IN A/W IPC-D-300G CLASS" at 209.55,65.151 h1.27
  text "3 LEVEL B" at 244.475,65.151 h1.27
  text "AS SHOWN" at 263.017,65.024 h1.27
  text "X" at 207.137,64.897 h1.52
  text "COPPER THICKNESS (FINISHED)" at 191.897,61.849 h1.27
  text "OUTER:" at 196.723,59.563 h1.27
  text "18um" at 209.804,59.563 h1.27
  text "35um" at 236.855,59.563 h1.27
  text "70um" at 263.144,59.563 h1.27
  text "X" at 234.112,59.36 h1.52
  text "INNER SIGNAL:" at 188.341,56.515 h1.27
  text "18um" at 209.804,56.515 h1.27
  text "35um" at 236.855,56.515 h1.27
  text "70um" at 263.144,56.515 h1.27
  text "X" at 234.061,56.312 h1.52
  text "INNER PWR:" at 192.024,53.467 h1.27
  text "18um" at 209.804,53.467 h1.27
  text "35um" at 236.855,53.467 h1.27
  text "70um" at 263.144,53.467 h1.27
  text "X" at 234.188,53.34 h1.52
  text "STRUCTURE:" at 184.15,50.419 h1.52
  text "REFER" at 209.804,50.419 h1.27
  text "AS PER DRAWING No." at 209.677,47.244 h1.27
  text "AS SHOWN" at 263.017,47.244 h1.27
  text "X" at 260.477,47.117 h1.52
  text "DRILLING:" at 184.15,44.45 h1.52
  text "VIEWED FROM:" at 189.103,42.164 h1.27
  text "COMPONENT SIDE" at 209.804,42.164 h1.14
  text "SOLDER SIDE" at 236.601,42.164 h1.14
  text "X" at 207.137,41.91 h1.52
  text "REFERENCE:" at 191.389,39.116 h1.27
  text "AS SHOWN" at 209.677,38.989 h1.14
  text "PATTERN MASTER LIST" at 236.728,38.989 h1.14
  text "X" at 260.477,38.989 h1.52
  text "NC_DRILL FILES" at 263.017,38.989 h1.14
  text "X" at 207.137,38.862 h1.52
  text "PTH MINIMUM COPPER THICKNESS:" at 197.231,36.068 h1.27
  text "20um" at 236.855,36.068 h1.27
  text "X" at 234.188,35.941 h1.52
  text "OTHER" at 263.017,35.941 h1.27
  text "NPTH:" at 197.739,33.02 h1.27
  text "TENTED" at 209.677,32.893 h1.14
  text "X" at 234.188,32.893 h1.52
  text "PADS REMOVED" at 236.728,32.893 h1.14
  text "REMOVE PADS" at 263.017,32.893 h1.14
  text "X" at 207.137,32.766 h1.52
  text "2nd DRILL" at 209.677,29.845 h1.14
  text "BOTH" at 236.728,29.845 h1.14
  text "AS SHOWN" at 249.047,29.845 h1.14
  text "NONE" at 263.017,29.845 h1.14
  text "BOARD FINISH:" at 184.15,26.924 h1.52
  text "X" at 207.137,26.797 h1.52
  text "ETCHING" at 209.677,26.797 h1.14
  text "REFER PATTERN MASTER LIST" at 236.728,26.797 h1.14
  text "LEGEND / SCREEN PRINT:" at 204.47,23.876 h1.27
  text "NONE" at 236.728,23.749 h1.14
  text "COMPONENT" at 249.047,23.749 h1.14
  text "SOLDER" at 263.017,23.749 h1.14
  text "X" at 246.507,23.622 h1.52
  text "X" at 260.477,23.622 h1.52
  text "COLOUR:" at 194.691,20.828 h1.27
  text "WHITE" at 209.677,20.701 h1.14
  text "YELLOW" at 236.728,20.701 h1.14
  text "OTHER" at 263.017,20.701 h1.14
  text "X" at 207.137,20.574 h1.52
  text "X" at 207.137,17.653 h1.52
  text "LIQUID PHOTOIMAGEABLE" at 209.677,17.653 h1.14
  text "SCREEN PRINT" at 249.047,17.653 h1.14
  text "MATTE" at 209.677,14.605 h1.14
  text "GLOSS" at 222.377,14.605 h1.14
  text "GREEN" at 236.728,14.605 h1.14
  text "BLUE" at 249.047,14.605 h1.14
  text "G/Y" at 263.017,14.605 h1.14
  text "OTHER" at 274.447,14.605 h1.14
  text "X" at 219.71,14.478 h1.52
  text "SOLDER MASK COLOUR:" at 184.15,11.684 h1.14
  text "BLACK" at 209.677,11.557 h1.14
  text "GREEN" at 222.377,11.557 h1.14
  text "YELLOW" at 236.728,11.557 h1.14
  text "BLUE" at 249.047,11.557 h1.14
  text "OTHER" at 263.017,11.557 h1.14
  text "X" at 207.01,11.43 h1.52
  text "TRACK FINISH:" at 184.15,8.636 h1.52
  text "SELECTIVE SOLDER (HASL)" at 209.677,8.509 h1.14
  text "REFLOW SOLDER" at 249.047,8.509 h1.14
  text "SELECTIVE GOLD" at 209.677,5.461 h1.14
  text "um  (AREA" at 236.728,5.461 h1.14
  text "sq. mm)" at 264.541,5.461 h1.14
  text "GOLD PLATED AS PER SAMPLE" at 256.159,3.175 h1.27
  text "REFER PATTERN MASTER LIST" at 209.677,2.413 h1.14
  text "X" at 246.507,2.413 h1.52
  text "OTHER" at 249.047,2.413 h1.14
  text "EDGE BOARD" at 184.15,-0.508 h1.52
  text "1.3um HARD GOLD OVER 5um     NICKEL / TIN-NICKEL" at 209.677,-0.635 h1.14
  text "CONTACTS:" at 184.15,-2.667 h1.52
  text "HARD FINISH GOLDE PLATE" at 209.677,-3.683 h1.14
  text "OTHER" at 249.047,-3.683 h1.14
  text "AS SHOWN" at 209.677,-6.731 h1.14
  text "REFER" at 249.047,-6.731 h1.14
  text "PROFILING:" at 184.15,-9.779 h1.52
  text "AS DIMENSIONED, MEASURED AND CUT FROM SPECIFIED DATUM." at 209.677,-9.779 h1.14
  text "X" at 207.137,-9.906 h1.52
  text "REFER PCB BLANK DWG No." at 209.804,-12.7 h1.27
  text "USE PROFILE / ROUTE TAPE SUPPLIED (REFER PATTERN MASTER LIST)" at 209.804,-15.748 h1.27
  text "SQUARE CUT" at 209.804,-18.796 h1.27
  text "N.C. ROUTE" at 227.584,-18.796 h1.27
  text "V. SCORE" at 245.364,-18.796 h1.27
  text "BLANK" at 263.144,-18.796 h1.27
  text "ACCEPTABILITY:" at 184.15,-21.463 h1.52
  text "MATERIALS AND WORKMANSHIP FOR ALL PRINTED WIRING BOARDS TO MEET" at 206.375,-21.59 h1.27
  text "OR EXCEED THE REQUIREMENTS OF:" at 206.375,-24.384 h1.27
  text "IPC-6011/12 AND IPC-A-600E" at 209.931,-27.051 h1.27
  text "1" at 245.491,-27.051 h1.27
  text "2" at 254.381,-27.051 h1.27
  text "X" at 251.714,-27.178 h1.52
  text "X" at 207.264,-27.305 h1.52
  text "3" at 263.271,-29.21 h1.27
  text "UL CERTIFICATION" at 209.931,-30.099 h1.27
  text "AUSTEL" at 245.491,-30.099 h1.27
  text "X" at 207.264,-30.226 h1.52
  text "ML-P-55110F GRP" at 209.423,-33.147 h1.02
  text "A" at 227.711,-33.147 h1.27
  text "B" at 236.601,-33.147 h1.27
  text "AS2546" at 245.491,-33.147 h1.27
  text "OTHER" at 263.271,-33.147 h1.27
  text "ADDITIONAL" at 184.15,-36.068 h1.52
  text "NONE" at 209.931,-36.322 h1.27
  text "SAMPLE PLAN" at 227.711,-36.322 h1.27
  text "MIL-P-55110E SERIAL Nos. PER ORDER" at 245.491,-36.322 h1.27
  text "REQUIREMENTS:" at 184.15,-38.481 h1.52
  text "NONE" at 209.931,-39.37 h1.27
  text "ML-P-55110F GRP" at 227.203,-39.37 h1.02
  text "A" at 245.491,-39.37 h1.27
  text "B" at 254.381,-39.37 h1.27
  text "IPC CLASS:" at 260.35,-39.37 h1.27
  text "1" at 275.844,-39.37 h1.27
  text "2" at 282.194,-39.37 h1.27
  text "3" at 288.544,-39.37 h1.27
  text "QUALITY RELEASE REPORT" at 227.711,-42.418 h1.27
  text "OTHER" at 268.224,-42.418 h1.27
  text "PER ORDER" at 276.733,-42.545 h1.27
  text "X" at 265.557,-42.672 h1.52
  text "NONE" at 227.711,-45.466 h1.27
  text "REQUIRED" at 245.491,-45.466 h1.27
  text "PER ORDER" at 268.351,-45.466 h1.27
  text "ELECTRICAL TEST:" at 184.15,-45.593 h1.52
  text "X" at 242.824,-45.593 h1.52
  text "NONE" at 227.711,-48.514 h1.27
  text "1 SIDE" at 245.364,-48.514 h1.14
  text "2 SIDES" at 256.54,-48.514 h1.14
  text "MIN. PITCH" at 268.224,-48.514 h1.27
  text "0.65mm" at 281.813,-48.514 h1.27
  text "SURFACE MOUNT:" at 184.15,-48.641 h1.52
  text "X" at 254.305,-48.717 h1.52
  text "NONE" at 227.711,-51.562 h1.27
  text "FOIL" at 245.491,-51.562 h1.27
  text "LEGEND" at 256.921,-51.562 h1.27
  text "REFER" at 268.224,-51.562 h1.27
  text "MANUFACTURER'S ID/LOGO:" at 184.15,-51.689 h1.52
  text "X" at 225.044,-51.816 h1.52
  text "ISO9001/AS3901" at 231.521,-54.61 h1.27
  text "NONE" at 268.224,-54.61 h1.27
  text "MANUFACTURER'S ACCREDITATION:" at 184.15,-54.737 h1.52
  text "X" at 228.854,-54.737 h1.52
  text "PER ORDER" at 227.711,-57.658 h1.27
  text "REFER" at 245.491,-57.658 h1.27
  text "PACKAGING AND HANDLING:" at 184.15,-57.785 h1.52
  text "X" at 225.044,-57.912 h1.52
Sheet:
  drawing of 1882 lines, arcs and shapes, not listed
  text "1" at -72.483,181.991 h1.78
  text "2" at -23.444,181.991 h1.78
  text "3" at 25.815,181.991 h1.78
  text "4" at 75.108,181.991 h1.78
  text "5" at 124.384,181.991 h1.78
  text "6" at 173.406,181.991 h1.78
  text "7" at 222.936,181.991 h1.78
  text "8" at 271.958,181.991 h1.78
  text "A" at -94.615,148.006 h1.78
  text "A" at 294.005,148.006 h1.78
  text "B" at -94.615,77.394 h1.78
  text "B" at 294.005,77.394 h1.78
  text "C" at -94.615,6.782 h1.78
  text "C" at 294.005,6.782 h1.78
  text "D" at -94.615,-63.322 h1.78
  text "D" at 294.005,-63.322 h1.78
  text "ENGINEER:" at 179.07,-63.5 h1.14
  text "TITLE:" at 217.17,-63.5 h1.14
  text "PCB DESIGNER:" at 179.07,-70.993 h1.14
  text "DATE:" at 179.07,-78.74 h1.14
  text "PART NO.:" at 217.17,-78.74 h1.14
  text "REV:" at 270.51,-78.74 h1.14
  text "Altium Limited" at 146.05,-81.28 h1.78
  text ".PRINT_DATE" at 180.34,-81.788 h1.78
  text "12a Rodborough Rd" at 146.05,-83.82 h1.78
  text "Frenchs Forest" at 146.05,-86.36 h1.78
  text "FILE NAME:" at 179.07,-86.36 h1.14
  text "DWG NO:" at 217.17,-86.36 h1.14
  text "SCALE:" at 270.51,-86.36 h1.14
  text "NSW 2086" at 146.05,-88.9 h1.78
  text ".PCB_FILE_NAME_NO_PATH" at 180.34,-89.408 h1.78
  text "1" at -72.483,-94.869 h1.78
  text "2" at -23.444,-94.869 h1.78
  text "3" at 25.815,-94.869 h1.78
  text "4" at 75.108,-94.869 h1.78
  text "5" at 124.384,-94.869 h1.78
  text "6" at 173.406,-94.869 h1.78
  text "7" at 222.936,-94.869 h1.78
  text "8" at 271.958,-94.869 h1.78
Drill Drawing:
  text ".Legend" at 0,-8 h0.75

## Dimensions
0,0 to 69,0 on Dimensions
0,0 to 0.001,77 on Dimensions
34.5,-69.801 to 39.6,85.2 on Dimensions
